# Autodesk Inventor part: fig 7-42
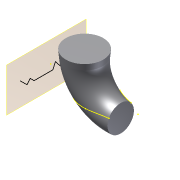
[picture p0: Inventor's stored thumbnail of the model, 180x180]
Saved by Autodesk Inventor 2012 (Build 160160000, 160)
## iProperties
Created: 2011-07
Part Number: fig 7-42
Material: Default
Document SubType Name: Modeling
Designer: CadCim
Density: 1 g/cm^3
Author: CadCim
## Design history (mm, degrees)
sketch "Sketch1"
  geometry: 1 further point
sketch "Sketch2"
  geometry: L1 (9, 5.1)-(9, 4.1); L2 (2.9, -2)-(2.9, -2); A1 r 6.1 centre (2.9, 4.1) between (2.9, -2) and (9, 4.1); 1 further point
  constraints: 4 end point, 2 point on circle, 2 tangent, 1 centre point, 1 perpendicular, 1 vertical
workplane "Work Plane1"
sketch "Sketch3"
  geometry: C1 r 2.236 at (0, 0); 1 further point
  constraints: 1 centre point
sweep "Sweep1" sketch "Sketch3" dims "d0" = 5 deg
workplane "Work Plane3"
sketch "Sketch5"
  geometry: L1 (5, -1)-(4, -1); L2 (4, -1)-(3, 0); L3 (3, 0)-(2.774, -1); L4 (2.774, -1)-(2, 0); L5 (2, 0)-(1.572, -1); L6 (1.572, -1)-(0.798, 0); L7 (0.798, 0)-(0.37, -1); L8 (0.37, -1)-(-2.804, -1); L9 (-2.804, -1)-(-3.466, -0.337); L10 (-3.466, -0.337)-(-4, -1); L11 (-4, -1)-(-5.153, 0.153); 1 further point
  constraints: 22 end point, 4 parallel, 1 collinear, 1 horizontal
sketch "3D Sketch1"
  node "Project from Sketch5"
body "Solid1"
other parameters: "d1" = -14.75
